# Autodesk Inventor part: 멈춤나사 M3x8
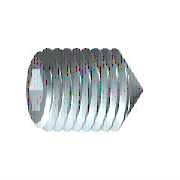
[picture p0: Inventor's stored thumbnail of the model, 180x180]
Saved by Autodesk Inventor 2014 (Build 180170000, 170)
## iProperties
IsCustomPart: 1
Created: 2012-02
Part Number: 멈춤나사 M3x8
Material: 강철, 연강
Description: 6각 소켓 머리 없는 멈춤 나사
Document SubType Name: Modeling
Standard: KS B 1028
Designer: test
Standards Organization: KS
Language: ko-KR
Size Designation: 원추점 M3x8
Categories: <MemberInstance><Categories><Category DisplayName="조임쇠" InternalName="e4da775c-781d-43d5-af7c-5136215cf5a6" Mnemonic="FSTN"><Category DisplayName="볼트" InternalN
Density: 7.86 g/cm^3
Appearance: 강철
Mass: 0.360339 g
Surface Area: 0.888172 cm^2
Volume: 0.0458447 cm^3
Author: test
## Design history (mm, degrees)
sketch "스케치1"
  geometry: L1 (0, 0)-(5.5, 0); L2 (8, 0.866)-(8, 1.5); L3 (8, 1.5)-(0, 1.5); L4 (8, 0.866)-(6, 0.866); L5 (6, 0.866)-(5.5, 0); L6 (0, -0.3)-(0, 1.8) reference; L7 (0, 1.5)-(0, 0)
  constraints: 13 end point, 3 parallel, 1 collinear, 1 perpendicular, 1 point on line
  dimensions: "d0" = 2 distance of L2.start L4.end (= INTI); "d1" = 60 deg angle of L5 L1; "d2" = 3 diameter of L3 L1 (= NND); "d3" = 1.73205 diameter of L4 L1 (= 1.1547 x SW); "d5" = 8 distance from line of L2 L3.end (= NLG)
revolve "본체" sketch "스케치1" stored, may be unused: angle "d6" = 90 deg
sketch "스케치2"
  geometry: L1 (-0.433, 0.75)-(0.433, 0.75); L2 (0.433, 0.75)-(0.866, 0); L3 (0.866, 0)-(0.433, -0.75); L4 (0.433, -0.75)-(-0.433, -0.75); L5 (-0.433, -0.75)-(-0.866, 0); L6 (-0.866, 0)-(-0.433, 0.75); 3 further points
  constraints: 12 end point, 1 coincident, 1 horizontal, 13 other
extrude "슬롯" join sketch "스케치2" taper "d7" = 0 deg; stored distance "d21" = 10
workaxis "Work Axis1"
workplane "Work Plane1"
sketch "스케치4"
  geometry: L1 (0, 0.15)-(-1.35, 1.5) reference; L2 (0, -0.15)-(-1.35, -1.5) reference; L3 (-1.35, -1.5)-(0.15, 0); L4 (-1.35, 1.5)-(0.15, 0); 2 further points
  constraints: 4 end point, 1 coincident, 1 collinear, 1 horizontal alignment
body "Solid1"
feature "스레드" dims "d12" = 8 (= NLG), "d13" = 0
chamfer "모따기1" distance "d8" = 1.35 (computed from NND, SPD, FAWI); stored, may be unused: angle "d9" = 45 deg (= FAWI), second distance "d34" = 1.35 (computed from NND, SPD, FAWI)
chamfer "모따기2" distance "d10" = 0.30673 (= -0.5 x GD1 + 0.5 x NND); stored, may be unused: angle "d11" = 45 deg (= FAWI), second distance "d35" = 0.30673 (= -0.5 x GD1 + 0.5 x NND)
other parameters: "NND" = 3 [user parameter; used in 5 equation terms], "NLG" = 8 [user parameter; used in 2 equation terms], "INTI" = 2 [user parameter; used in 1 equation term], "FAWI" = 45 deg [user parameter; used in 4 equation terms], "SW" = 1.5 [user parameter; used in 2 equation terms], "GD1" = 2.38655 (= THREADDIA - 1.2269 x PTC) [user parameter; used in 2 equation terms], "d4" = 0, "FAWI1" = 45 deg [user parameter], "SPD" = 0.3 [user parameter; used in 2 equation terms], "d36" = 0, "d37" = 0, "GUL" = 0.30673 (= 0.61345 x PTC) [user parameter], "TOA" = 30 deg [user parameter], "THREADDIA" = 3 [user parameter; used in 1 equation term], "PTC" = 0.5 [user parameter; used in 4 equation terms], "GAL" = 0.30673 (= 0.61345 x PTC) [user parameter], "E0" = 1.7325 (= 1.155 x SW) [user parameter]
